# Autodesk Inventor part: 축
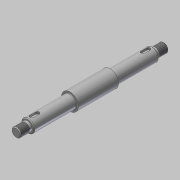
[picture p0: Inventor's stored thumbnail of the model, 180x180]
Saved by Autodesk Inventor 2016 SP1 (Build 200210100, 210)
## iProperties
Created: 2018-11
Part Number: 축
Material: 강철, 연강
Document SubType Name: Modeling
Designer: mduedu
Density: 1 g/cm^3
Appearance: 강철
Author: mduedu
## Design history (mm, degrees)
sketch "스케치1"
  geometry: L1 (-26, 0)-(26, 0); L2 (26, 0)-(26, 11); L3 (26, 11)-(-26, 11); L4 (-26, 11)-(-26, 0); L5 (-26, 0)-(-81, 0); L6 (-81, 0)-(-81, 8.5); L7 (-81, 8.5)-(-26, 8.5); L8 (-26, 8.5)-(-26, 0); L9 (-81, 0)-(-96, 0); L10 (-96, 0)-(-96, 6); L11 (-96, 6)-(-81, 6); L12 (-81, 6)-(-81, 0); L13 (0, 0)-(0, 11); L14 (26, 0)-(81, 0); L15 (81, 0)-(81, 8.5); L16 (81, 8.5)-(26, 8.5); L17 (26, 8.5)-(26, 0); L18 (81, 0)-(96, 0); L19 (96, 0)-(96, 6); L20 (96, 6)-(81, 6); L21 (81, 6)-(81, 0); 1 further point
  constraints: 42 end point, 6 parallel, 6 symmetric about line, 3 horizontal, 3 perpendicular, 2 midpoint, 1 coincident
  dimensions: "d0" = 22 diameter of L3 L1; "d2" = 17 diameter of L7 L5; "d3" = 12 diameter of L11 L9; "d4" = 52 distance of L2.end L3.end; "d5" = 55 distance of L6.end L7.end; "d6" = 192 distance between parallel lines of L19 L10
revolve "회전1" sketch "스케치1" stored, may be unused: angle "d7" = 90 deg
fillet "모깎기1" dims "d8" = 0.6
node "작업 평면1"
sketch "스케치2" dims "d11" = 12
  geometry: L1 (15, 2.5)-(22, 2.5); L2 (22, 2.5)-(22, -2.5); L3 (22, -2.5)-(15, -2.5); L4 (15, -2.5)-(15, 2.5); L5 (27.5, 8.5)-(27.5, -8.5) reference; 3 further points
  constraints: 8 end point, 2 midpoint, 2 parallel, 2 vertical alignment, 1 horizontal, 1 horizontal alignment, 1 perpendicular, 4 other
  dimensions: "d9" = 3 dimension on L5; "d10" = 5 distance between parallel lines of L3 L1
extrude "돌출1" cut sketch "스케치2" distance "d12" = 3; taper "d13" = 0 deg
chamfer "모따기1" distance "d14" = 1; stored, may be unused: second distance "d15" = 2, angle "d16" = 45 deg
feature "스레드1" dims "d17" = 12, "d18" = 0
feature "스레드2" dims "d19" = 12, "d20" = 0
chamfer "모따기2" distance "d21" = 1; stored, may be unused: second distance "d22" = 2, angle "d23" = 45 deg
node "솔리드1"
mirror "대칭1"
